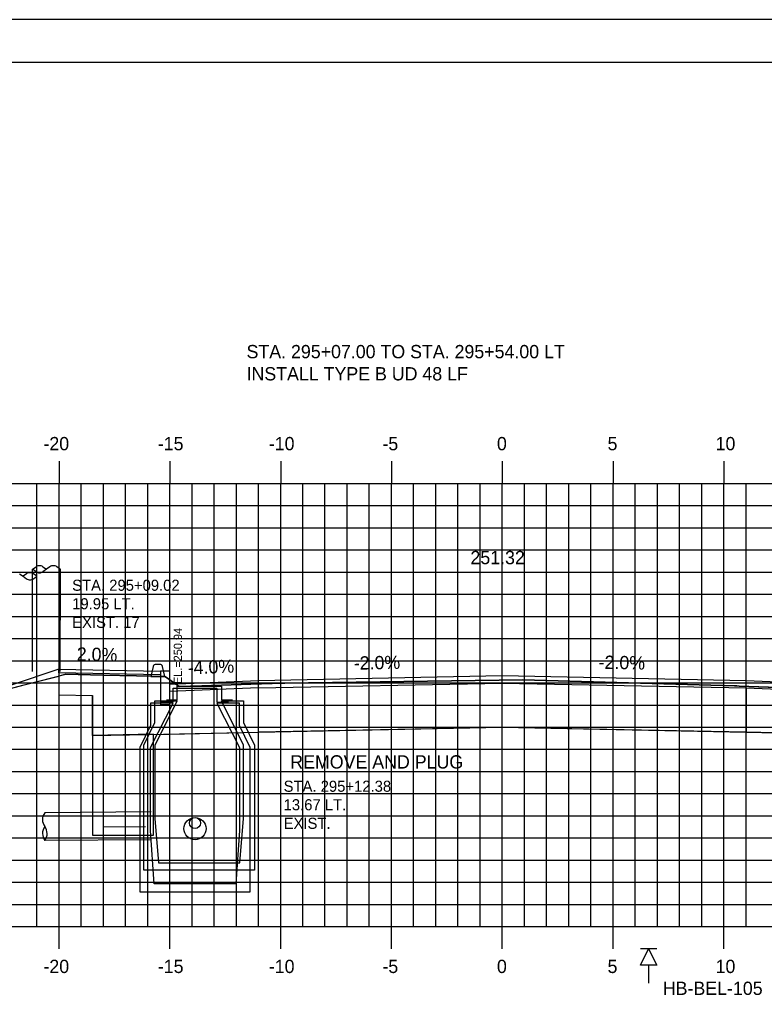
# Model space of a CAD drawing. Extents: x 859352 to 859522, y 366268 to 366378.
# Drawn here: x 859413.35 to 859446.96, y 366333.95 to 366378.18 of the extents above; entities that cross this region are included whole.
import ezdxf

# ---------------------------------------------------------------- set-up
doc = ezdxf.new("R2010")
doc.units = 0
for name, color, linetype in [('ANNOTATION', 7, 'Continuous'), ('BORDER', 7, 'Continuous'), ('D_Curb_Type_1_Lt', 7, 'Continuous'), ('D_Drainage_CB_TypeA1-B1', 7, 'Continuous'), ('D_Drainage_Culvert', 7, 'Continuous'), ('D_Drainage_Text', 7, 'Continuous'), ('D_Roadway_Centerline', 7, 'Continuous'), ('D_Roadway_Centerline_Text', 7, 'Continuous'), ('D_Roadway_Edge_Shoulder', 7, 'Continuous'), ('D_Roadway_FinishedGrade', 7, 'Continuous'), ('D_Roadway_Sidewalks_Paved', 7, 'Continuous'), ('D_Roadway_SubGrade', 7, 'Continuous'), ('D_Text_Monospaced', 7, 'Continuous'), ('D_Text_Standard', 7, 'Continuous'), ('D_Utilities_Pole_Joint', 7, 'Continuous'), ('H_V ANNOTATION', 7, 'Continuous'), ('JUNK COM EXC', 7, 'Continuous'), ('JUNK FILL', 7, 'Continuous'), ('junk strct exc', 7, 'Continuous'), ('MAJOR', 7, 'Continuous'), ('MINOR', 7, 'Continuous'), ('PDRAIN', 7, 'Continuous'), ('PLOT BOUNDARY', 7, 'Continuous'), ('ROCKS', 7, 'Continuous'), ('S_Curb_Type_3', 7, 'Continuous'), ('S_Drainage_CB', 7, 'Continuous'), ('S_Roadway_Centerline', 7, 'Continuous'), ('S_Utilities_Pole_Power', 7, 'Continuous')]:
    doc.layers.add(name, color=color, linetype=linetype)

msp = doc.modelspace()

# ---------------------------------------------------------------- linework, layer by layer
at = {"layer": 'ANNOTATION'}
msp.add_line((859419.025, 366341.729), (859417.152, 366341.716), dxfattribs=at)
at = {"layer": 'BORDER'}
msp.add_line((859520.13, 366376.236), (859360.13, 366376.236), dxfattribs=at)
at = {"layer": 'D_Curb_Type_1_Lt'}
msp.add_lwpolyline([(859419.713, 366348.764), (859419.713, 366347.264), (859420.129, 366347.264), (859420.129, 366348.764)], close=True, dxfattribs=at)
at = {"layer": 'D_Drainage_CB_TypeA1-B1'}
for p, q in [((859419.261, 366347.325), (859419.261, 366346.308)), ((859419.261, 366345.324), (859420.278, 366347.325)), ((859420.278, 366347.325), (859419.261, 366347.325)), ((859423.264, 366347.325), (859422.247, 366347.325)), ((859422.247, 366347.325), (859423.264, 366345.324)), ((859423.264, 366346.308), (859423.264, 366347.325)), ((859419.261, 366346.308), (859418.769, 366345.324)), ((859423.756, 366345.324), (859423.264, 366346.308)), ((859418.769, 366345.324), (859418.769, 366338.796)), ((859419.261, 366341.574), (859419.261, 366345.324)), ((859423.264, 366345.324), (859423.264, 366341.574)), ((859423.756, 366338.796), (859423.756, 366345.324)), ((859419.425, 366339.156), (859419.261, 366341.574)), ((859423.264, 366341.574), (859423.1, 366339.156)), ((859423.1, 366339.156), (859419.425, 366339.156)), ((859418.769, 366338.796), (859423.756, 366338.796))]:
    msp.add_line(p, q, dxfattribs=at)
msp.add_lwpolyline([(859419.754, 366347.367), (859420.278, 366347.367), (859420.278, 366347.99), (859422.247, 366347.99), (859422.247, 366347.367), (859422.772, 366347.367)], dxfattribs=at)
at = {"layer": 'D_Drainage_Culvert'}
for p, q in [((859419.29, 366342.407), (859414.48, 366342.373)), ((859419.29, 366341.156), (859414.489, 366341.123))]:
    msp.add_line(p, q, dxfattribs=at)
msp.add_circle((859421.263, 366341.906), 0.25, dxfattribs=at)
for centre, start, end in [((859414.899, 366342.063), 143.5312, 217.271), ((859414.903, 366341.438), 143.5312, 217.271), ((859414.07, 366341.432), 323.5312, 37.271)]:
    msp.add_arc(centre, 0.521, start, end, dxfattribs=at)
at = {"layer": 'D_Roadway_Centerline'}
msp.add_lwpolyline([(859424.129, 366348.341), (859435.129, 366348.561), (859446.129, 366348.341)], dxfattribs=at)
at = {"layer": 'D_Roadway_Edge_Shoulder'}
msp.add_lwpolyline([(859420.129, 366348.181), (859424.129, 366348.341), (859435.129, 366348.561), (859446.129, 366348.341), (859450.121, 366348.181)], dxfattribs=at)
at = {"layer": 'D_Roadway_FinishedGrade'}
msp.add_lwpolyline([(859415.124, 366348.856), (859410.842, 366347.428)], dxfattribs=at)
at = {"layer": 'D_Roadway_Sidewalks_Paved'}
msp.add_lwpolyline([(859415.124, 366348.856), (859419.713, 366348.764), (859419.713, 366348.597), (859415.124, 366348.689)], close=True, dxfattribs=at)
at = {"layer": 'D_Roadway_SubGrade'}
for p, q in [((859415.124, 366348.689), (859415.124, 366347.689)), ((859424.129, 366348.007), (859420.129, 366347.847)), ((859415.124, 366347.689), (859416.644, 366347.659)), ((859416.644, 366345.858), (859416.644, 366347.659)), ((859420.129, 366345.927), (859424.129, 366346.007)), ((859419.129, 366345.907), (859416.644, 366345.858)), ((859419.129, 366345.907), (859420.129, 366345.927))]:
    msp.add_line(p, q, dxfattribs=at)
for points in [[(859424.129, 366346.007), (859424.129, 366348.007), (859435.129, 366348.227), (859446.129, 366348.007), (859446.129, 366346.007), (859435.129, 366346.227)], [(859446.129, 366348.007), (859450.129, 366347.847), (859450.129, 366345.927), (859446.129, 366346.007)]]:
    msp.add_lwpolyline(points, close=True, dxfattribs=at)
at = {"layer": 'D_Utilities_Pole_Joint'}
for p, q in [((859413.348, 366353.159), (859413.504, 366353.048)), ((859413.66, 366353.159), (859413.504, 366353.048)), ((859414.129, 366353.048), (859413.973, 366353.159)), ((859413.504, 366353.048), (859413.66, 366352.937)), ((859413.973, 366352.937), (859414.129, 366353.048)), ((859414.129, 366348.29), (859414.129, 366353.048))]:
    msp.add_line(p, q, dxfattribs=at)
for centre, start, end in [((859413.817, 366352.938), 90, 125.2644), ((859413.817, 366352.938), 54.7356, 90), ((859413.817, 366353.159), 234.7356, 270), ((859413.817, 366353.159), 270, 305.2644)]:
    msp.add_arc(centre, 0.271, start, end, dxfattribs=at)
at = {"layer": 'JUNK COM EXC'}
msp.add_lwpolyline([(859451.129, 366347.905), (859445.818, 366348.091), (859445.715, 366348.095), (859445.604, 366348.098), (859436.054, 366348.372), (859425.319, 366348.22), (859424.742, 366348.213), (859423.783, 366348.18), (859421.575, 366348.105), (859420.543, 366348.079), (859419.973, 366348.478), (859419.901, 366348.53), (859418.627, 366348.55), (859417.106, 366348.582), (859415.438, 366348.625), (859415.124, 366348.545), (859415.124, 366347.689), (859416.644, 366347.659), (859416.644, 366345.858), (859419.129, 366345.907), (859424.129, 366346.007), (859435.129, 366346.236), (859446.129, 366346.007), (859451.129, 366345.907)], close=True, dxfattribs=at)
at = {"layer": 'JUNK FILL'}
msp.add_lwpolyline([(859415.129, 366348.546), (859415.129, 366348.856), (859415.124, 366348.856), (859410.842, 366347.428), (859413.548, 366348.142), (859415.124, 366348.545)], close=True, dxfattribs=at)
at = {"layer": 'junk strct exc'}
msp.add_lwpolyline([(859416.644, 366345.858), (859416.644, 366341.366), (859419.394, 366341.366), (859419.394, 366345.913)], close=True, dxfattribs=at)
at = {"layer": 'MAJOR'}
for p, q in [((859415.129, 366358.238), (859415.129, 366357.236)), ((859420.129, 366358.238), (859420.129, 366357.236)), ((859425.129, 366358.238), (859425.129, 366357.236)), ((859430.129, 366358.238), (859430.129, 366357.236)), ((859435.129, 366358.238), (859435.129, 366357.236)), ((859440.129, 366358.238), (859440.129, 366357.236)), ((859445.129, 366358.238), (859445.129, 366357.236)), ((859365.129, 366357.236), (859505.129, 366357.236)), ((859365.129, 366357.236), (859505.129, 366357.236)), ((859415.129, 366337.236), (859415.129, 366357.236)), ((859420.129, 366337.236), (859420.129, 366357.236)), ((859425.129, 366337.236), (859425.129, 366357.236)), ((859430.129, 366337.236), (859430.129, 366357.236)), ((859435.129, 366337.236), (859435.129, 366357.236)), ((859440.129, 366337.236), (859440.129, 366357.236)), ((859445.129, 366337.236), (859445.129, 366357.236)), ((859365.129, 366352.236), (859505.129, 366352.236)), ((859365.129, 366347.236), (859505.129, 366347.236)), ((859365.129, 366342.236), (859505.129, 366342.236)), ((859365.129, 366337.236), (859505.129, 366337.236)), ((859365.129, 366337.236), (859505.129, 366337.236)), ((859415.129, 366336.234), (859415.129, 366337.236)), ((859420.129, 366336.234), (859420.129, 366337.236)), ((859425.129, 366336.234), (859425.129, 366337.236)), ((859430.129, 366336.234), (859430.129, 366337.236)), ((859435.129, 366336.234), (859435.129, 366337.236)), ((859440.129, 366336.234), (859440.129, 366337.236)), ((859445.129, 366336.234), (859445.129, 366337.236))]:
    msp.add_line(p, q, dxfattribs=at)
at = {"layer": 'MINOR'}
for p, q in [((859414.129, 366337.236), (859414.129, 366357.236)), ((859416.129, 366337.236), (859416.129, 366357.236)), ((859417.129, 366337.236), (859417.129, 366357.236)), ((859418.129, 366337.236), (859418.129, 366357.236)), ((859419.129, 366337.236), (859419.129, 366357.236)), ((859421.129, 366337.236), (859421.129, 366357.236)), ((859422.129, 366337.236), (859422.129, 366357.236)), ((859423.129, 366337.236), (859423.129, 366357.236)), ((859424.129, 366337.236), (859424.129, 366357.236)), ((859426.129, 366337.236), (859426.129, 366357.236)), ((859427.129, 366337.236), (859427.129, 366357.236)), ((859428.129, 366337.236), (859428.129, 366357.236)), ((859429.129, 366337.236), (859429.129, 366357.236)), ((859431.129, 366337.236), (859431.129, 366357.236)), ((859432.129, 366337.236), (859432.129, 366357.236)), ((859433.129, 366337.236), (859433.129, 366357.236)), ((859434.129, 366337.236), (859434.129, 366357.236)), ((859436.129, 366337.236), (859436.129, 366357.236)), ((859437.129, 366337.236), (859437.129, 366357.236)), ((859438.129, 366337.236), (859438.129, 366357.236)), ((859439.129, 366337.236), (859439.129, 366357.236)), ((859441.129, 366337.236), (859441.129, 366357.236)), ((859442.129, 366337.236), (859442.129, 366357.236)), ((859443.129, 366337.236), (859443.129, 366357.236)), ((859444.129, 366337.236), (859444.129, 366357.236)), ((859446.129, 366337.236), (859446.129, 366357.236)), ((859365.129, 366356.236), (859505.129, 366356.236)), ((859365.129, 366355.236), (859505.129, 366355.236)), ((859365.129, 366354.236), (859505.129, 366354.236)), ((859365.129, 366353.236), (859505.129, 366353.236)), ((859365.129, 366351.236), (859505.129, 366351.236)), ((859365.129, 366350.236), (859505.129, 366350.236)), ((859365.129, 366349.236), (859505.129, 366349.236)), ((859365.129, 366348.236), (859505.129, 366348.236)), ((859365.129, 366346.236), (859505.129, 366346.236)), ((859365.129, 366345.236), (859505.129, 366345.236)), ((859365.129, 366344.236), (859505.129, 366344.236)), ((859365.129, 366343.236), (859505.129, 366343.236)), ((859365.129, 366341.236), (859505.129, 366341.236)), ((859365.129, 366340.236), (859505.129, 366340.236)), ((859365.129, 366339.236), (859505.129, 366339.236)), ((859365.129, 366339.236), (859505.129, 366339.236)), ((859365.129, 366338.236), (859505.129, 366338.236))]:
    msp.add_line(p, q, dxfattribs=at)
at = {"layer": 'PDRAIN'}
msp.add_circle((859421.263, 366341.656), 0.5, dxfattribs=at)
at = {"layer": 'PLOT BOUNDARY'}
msp.add_lwpolyline([(859352.036, 366268.177), (859522.036, 366268.177), (859522.036, 366378.177), (859352.036, 366378.177)], close=True, dxfattribs=at)
at = {"layer": 'ROCKS'}
for p, q in [((859442.098, 366336.236), (859441.36, 366336.236)), ((859441.729, 366335.498), (859441.729, 366334.684))]:
    msp.add_line(p, q, dxfattribs=at)
msp.add_lwpolyline([(859441.729, 366336.236), (859442.098, 366335.498), (859441.36, 366335.498)], close=True, dxfattribs=at)
at = {"layer": 'S_Curb_Type_3'}
for points in [[(859419.379, 366348.974), (859419.276, 366348.53), (859419.901, 366348.53), (859419.798, 366348.974)], [(859419.676, 366349.071), (859419.5, 366349.071)]]:
    msp.add_lwpolyline(points, dxfattribs=at)
for centre, start, end in [((859419.5, 366348.946), 90, 167.0054), ((859419.676, 366348.946), 12.9946, 90)]:
    msp.add_arc(centre, 0.125, start, end, dxfattribs=at)
at = {"layer": 'S_Drainage_CB'}
for p, q in [((859419.446, 366346.444), (859419.446, 366347.428)), ((859419.446, 366347.428), (859420.463, 366347.428)), ((859420.463, 366347.428), (859419.446, 366345.426)), ((859422.465, 366347.428), (859423.449, 366347.428)), ((859423.449, 366345.426), (859422.465, 366347.428)), ((859423.449, 366347.428), (859423.449, 366346.444)), ((859418.954, 366345.426), (859419.446, 366346.444)), ((859423.449, 366346.444), (859423.941, 366345.426)), ((859418.954, 366339.783), (859418.954, 366345.426)), ((859419.446, 366345.426), (859419.446, 366342.113)), ((859423.449, 366342.113), (859423.449, 366345.426)), ((859423.941, 366345.426), (859423.941, 366339.783)), ((859419.446, 366342.113), (859419.61, 366340.112)), ((859423.285, 366340.112), (859423.449, 366342.113)), ((859419.61, 366340.112), (859423.285, 366340.112)), ((859423.941, 366339.783), (859418.954, 366339.783))]:
    msp.add_line(p, q, dxfattribs=at)
msp.add_lwpolyline([(859419.971, 366347.469), (859420.463, 366347.469), (859420.463, 366348.093), (859422.465, 366348.093), (859422.465, 366347.469), (859422.957, 366347.469)], dxfattribs=at)
at = {"layer": 'S_Roadway_Centerline'}
msp.add_lwpolyline([(859406.139, 366346.189), (859413.548, 366348.142), (859415.438, 366348.625), (859417.106, 366348.582), (859418.627, 366348.55), (859419.901, 366348.53), (859419.973, 366348.478), (859420.543, 366348.079), (859421.575, 366348.105), (859423.783, 366348.18), (859424.742, 366348.213), (859425.319, 366348.22), (859436.054, 366348.372), (859445.604, 366348.098), (859445.715, 366348.095), (859445.818, 366348.091), (859453.662, 366347.816)], dxfattribs=at)
at = {"layer": 'S_Utilities_Pole_Power'}
for p, q in [((859413.933, 366353.366), (859414.09, 366353.476)), ((859413.933, 366348.746), (859413.937, 366353.366)), ((859414.09, 366353.255), (859413.933, 366353.366)), ((859414.402, 366353.476), (859414.559, 366353.366)), ((859414.559, 366353.366), (859414.402, 366353.255)), ((859414.715, 366353.476), (859414.559, 366353.366)), ((859415.183, 366353.366), (859415.027, 366353.476)), ((859415.183, 366348.746), (859415.187, 366353.366))]:
    msp.add_line(p, q, dxfattribs=at)
for centre, start, end in [((859414.246, 366353.255), 90, 125.2644), ((859414.246, 366353.255), 54.7356, 90), ((859414.871, 366353.255), 90, 125.2644), ((859414.871, 366353.255), 54.7356, 90), ((859414.246, 366353.476), 234.7356, 270), ((859414.246, 366353.476), 270, 305.2644)]:
    msp.add_arc(centre, 0.271, start, end, dxfattribs=at)

# ---------------------------------------------------------------- texts
at = {"layer": 'ANNOTATION'}
for s, rotation, p in [('2.0%', 358.8542, (859415.922, 366349.24)), ('-4.0%', 2.2906, (859420.945, 366348.614)), ('-2.0%', 1.1458, (859428.432, 366348.827)), ('-2.0%', 358.8542, (859439.472, 366348.874))]:
    msp.add_text(s, height=0.6, rotation=rotation, dxfattribs=at).set_placement(p)
at = {"layer": 'D_Drainage_Text'}
for s, p in [('STA. 295+07.00 TO STA. 295+54.00 LT', (859423.589, 366362.889)), ('INSTALL TYPE B UD 48 LF', (859423.589, 366361.889))]:
    msp.add_text(s, height=0.6, dxfattribs=at).set_placement(p)
at = {"layer": 'D_Roadway_Centerline_Text'}
msp.add_text('251.32', height=0.6, dxfattribs=at).set_placement((859433.693, 366353.593))
at = {"layer": 'D_Text_Monospaced'}
for s, height, p in [('STA. 295+09.02', 0.49998, (859415.72, 366352.392)), ('19.95 LT.', 0.5, (859415.72, 366351.558)), ('EXIST. 17', 0.5, (859415.72, 366350.718)), ('STA. 295+12.38', 0.49998, (859425.263, 366343.319)), ('13.67 LT.', 0.5, (859425.263, 366342.485)), ('EXIST. ', 0.5, (859425.263, 366341.645))]:
    msp.add_text(s, height=height, dxfattribs=at).set_placement(p)
at = {"layer": 'D_Text_Standard'}
msp.add_text(' EL.=250.94', height=0.36848, rotation=90, dxfattribs=at).set_placement((859420.672, 366348.045))
msp.add_text('REMOVE AND PLUG', height=0.6, dxfattribs=at).set_placement((859425.562, 366344.368))
at = {"layer": 'H_V ANNOTATION'}
for s, p in [('-20', (859414.423, 366358.736)), ('-15', (859419.586, 366358.736)), ('-10', (859424.594, 366358.736)), ('-5', (859429.72, 366358.736)), ('0', (859434.888, 366358.736)), ('5', (859439.88, 366358.736)), ('10', (859444.755, 366358.736)), ('-20', (859414.423, 366335.136)), ('-15', (859419.586, 366335.136)), ('-10', (859424.594, 366335.136)), ('-5', (859429.72, 366335.136)), ('0', (859434.888, 366335.136)), ('5', (859439.88, 366335.136)), ('10', (859444.755, 366335.136))]:
    msp.add_text(s, height=0.6, dxfattribs=at).set_placement(p)
at = {"layer": 'ROCKS'}
msp.add_text('HB-BEL-105', height=0.6, dxfattribs=at).set_placement((859442.373, 366334.147))
at = {"layer": 'S_Roadway_Centerline'}
for s, p in [('C', (859436.049, 366348.372)), ('L', (859436.054, 366348.365))]:
    msp.add_text(s, height=0.0146, dxfattribs=at).set_placement(p)

doc.saveas('drawing.dxf')
